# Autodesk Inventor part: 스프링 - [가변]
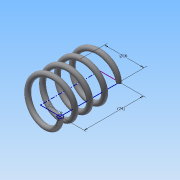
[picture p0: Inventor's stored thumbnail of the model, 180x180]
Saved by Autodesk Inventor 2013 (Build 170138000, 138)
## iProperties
Created: 2015-04
Part Number: 스프링 - [가변]
Material: 강철, 탄소
Document SubType Name: Modeling
Designer: Administrator
Density: 7.87 g/cm^3
Mass: 4.8666 g
Surface Area: 12.5993 cm^2
Volume: 0.618374 cm^3
Author: Administrator
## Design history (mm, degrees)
sketch "스케치1"
  geometry: L1 (0, 0)-(8, 0); L2 (8, 0)-(8, 20.5); L3 (8, 20.5)-(0, 20.5); L4 (0, 20.5)-(0, 0); C1 r 1 at (8, 0)
  constraints: 8 end point, 2 parallel, 1 centre point, 1 coincident, 1 horizontal, 1 perpendicular
  dimensions: "d0" = 16 diameter of L2 L4; "d2" = 20.49951 distance of L1.end L2.end (derived); "d3" = 2 diameter of C1
feature "코일1" pitch "d4" = 10; turns "d6" = 4; dims "d5" = 20.49951 (= d2), "d7" = 0, angle "d8" = 90 deg, angle "d9" = 90 deg, "d10" = 0, "d11" = 0
node "작업 평면1"
sketch "스케치2"
  geometry: L1 (-9, 0)-(-7, 0) reference; 1 further point
  constraints: 1 horizontal alignment
extrude "돌출1" cut sketch "스케치2" stored distance "d13" = 10; taper "d14" = 0 deg
node "작업 평면2"
sketch "스케치3"
  geometry: L1 (-7, 0)-(-9, 0) reference; 1 further point
  constraints: 1 horizontal alignment
extrude "돌출2" cut sketch "스케치3" stored distance "d16" = 10; taper "d17" = 0 deg
node "솔리드1"
node "절단 모서리 투영1"
node "절단 모서리 투영2"
other parameters: "d12" = 0, "d15" = 20.49951 (= d2)
